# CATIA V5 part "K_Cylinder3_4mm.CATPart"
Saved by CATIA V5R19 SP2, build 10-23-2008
Part number: Cylinder3
Bounding box of the stored display mesh (mm): x 0 to 4, y -0.5 to 0.5, z -0.5 to 0.5
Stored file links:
  G:\Khaled_CFAO_2011\ST2M\ST2M_GR1\bgaltie\bgaltie\Khaled\CAD_thinkMOTION\K_Cylinder3_4mm.CATPart
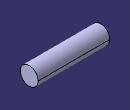
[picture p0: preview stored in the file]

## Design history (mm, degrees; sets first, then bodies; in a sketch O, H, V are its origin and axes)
AxisSystem1: origin (0, 0, 0), X (1, 0, 0), Y (0, 1, 0), Z (0, 0, 1)
Body1 (main body)
  Sketch1 on YZ plane of AxisSystem1, origin (0, 0, 0), H (0, 1, 0), V (0, 0, 1)
    circle A1 centre (0, 0) radius 0.5
    radius A1 = 0.5
  Pad1: profile Sketch1, direction (1, 0, 0), length 4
